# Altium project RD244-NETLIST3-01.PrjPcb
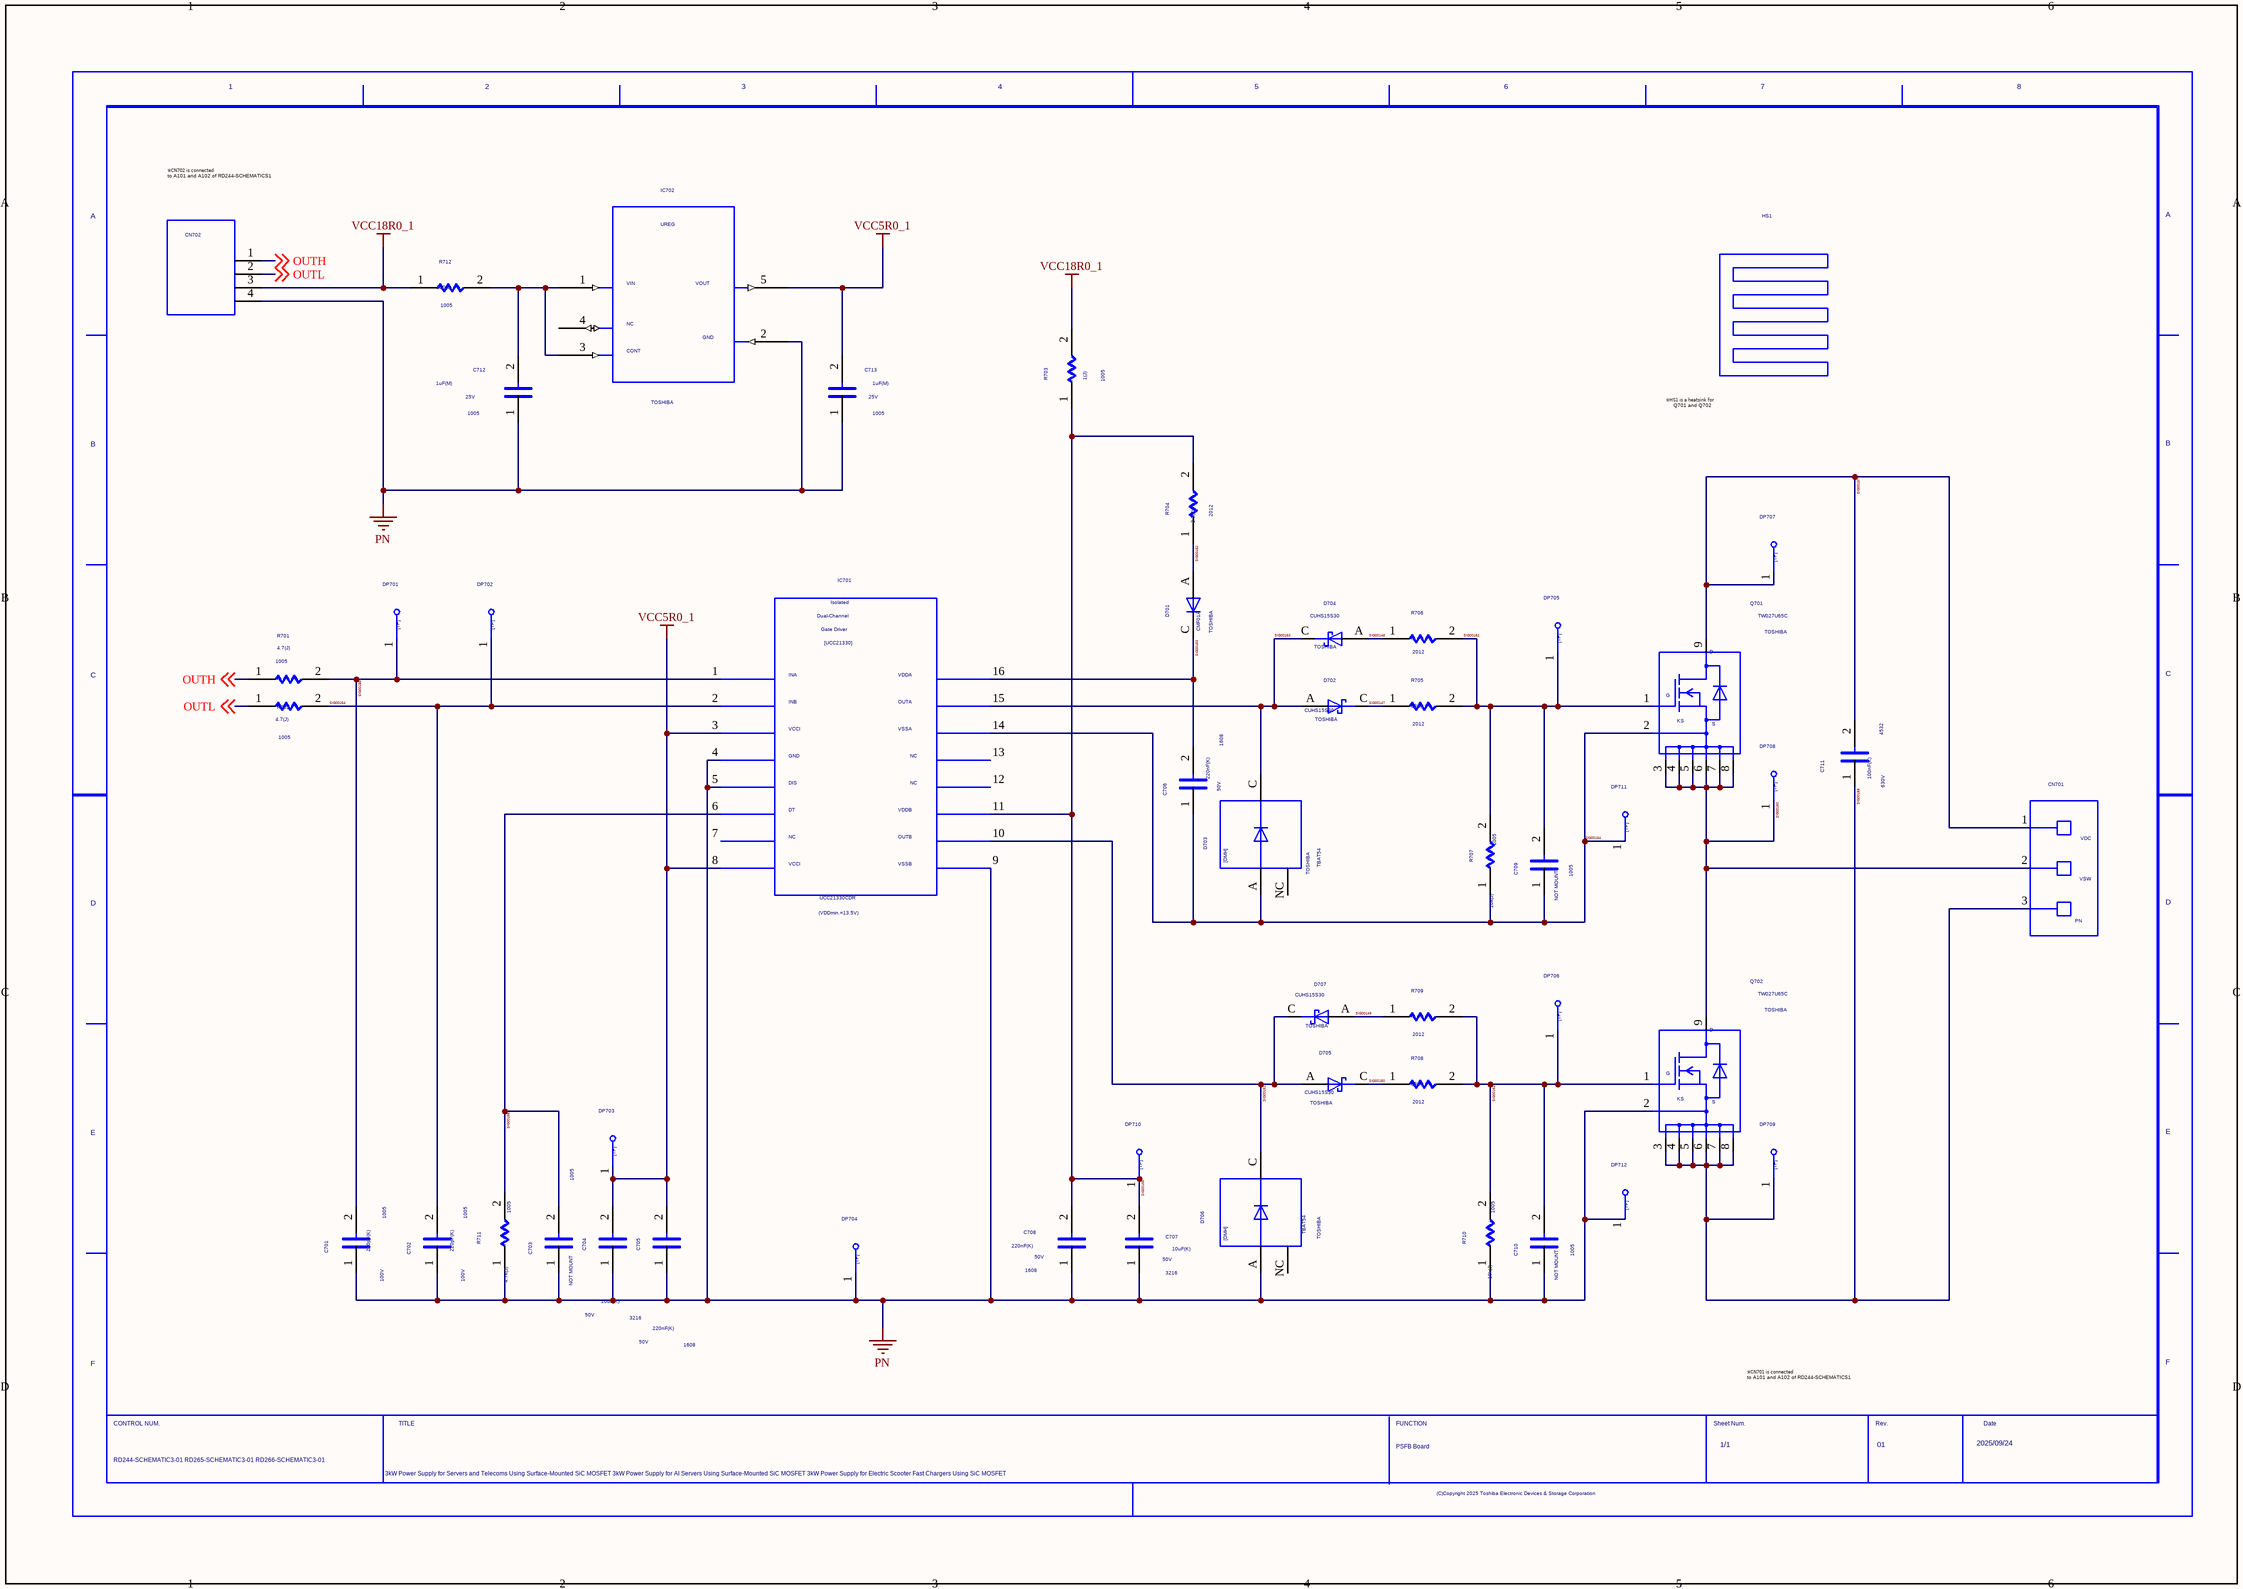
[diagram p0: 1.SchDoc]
1 sheet, 52 parts. Net scope: global (net labels, ports and power ports of the same name join across sheets).

## Sheet 1.SchDoc
size 420 x 297 mm

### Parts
C701  VAL1: 220pF(K)  VAL2: 100V  SIZECODESMD: 1005  (hidden comment: C)
C702  VAL1: 220pF(K)  VAL2: 100V  SIZECODESMD: 1005  (hidden comment: C)
C703  NOTMOUNT: NOT MOUNT  SIZECODESMD: 1005  (hidden comment: C)
C704  VAL1: 10uF(K)  VAL2: 50V  SIZECODESMD: 3216  (hidden comment: C)
C705  VAL1: 220nF(K)  VAL2: 50V  SIZECODESMD: 1608  (hidden comment: C1608)
C706  VAL1: 220nF(K)  VAL2: 50V  SIZECODESMD: 1608  (hidden comment: C1608)
C707  VAL1: 10uF(K)  VAL2: 50V  SIZECODESMD: 3216  (hidden comment: C)
C708  VAL1: 220nF(K)  VAL2: 50V  SIZECODESMD: 1608  (hidden comment: C1608)
C709  NOTMOUNT: NOT MOUNT  SIZECODESMD: 1005  (hidden comment: C)
C710  NOTMOUNT: NOT MOUNT  SIZECODESMD: 1005  (hidden comment: C)
C711  VAL1: 100nF(K)  VAL2: 630V  SIZECODESMD: 4532  (hidden comment: C)
C712  VAL1: 1uF(M)  VAL2: 25V  SIZECODESMD: 1005  (hidden comment: C)
C713  VAL1: 1uF(M)  VAL2: 25V  SIZECODESMD: 1005  (hidden comment: C)
CN701  RD-244_CN_from_FB  (value not drawn)
CN702  TSW-104-08-G-S-RA  (value not drawn)
D701  USERCOMPTEXT3: TOSHIBA  VAL3: CMF01A  (hidden comment: D)
D702  USERCOMPTEXT3: TOSHIBA  (hidden comment: CUHS15S30)
D703  USERCOMPTEXT3: TOSHIBA  VAL3: TBAT54  (hidden comment: DMH)
D704  USERCOMPTEXT3: TOSHIBA  (hidden comment: CUHS15S30)
D705  USERCOMPTEXT3: TOSHIBA  (hidden comment: CUHS15S30)
D706  USERCOMPTEXT3: TOSHIBA  VAL3: TBAT54  (hidden comment: DMH)
D707  USERCOMPTEXT3: TOSHIBA  (hidden comment: CUHS15S30)
DP701  TP  (value not drawn)
DP702  TP  (value not drawn)
DP703  TP  (value not drawn)
DP704  TP  (value not drawn)
DP705  TP  (value not drawn)
DP706  TP  (value not drawn)
DP707  TP  (value not drawn)
DP708  TP  (value not drawn)
DP709  TP  (value not drawn)
DP710  TP  (value not drawn)
DP711  TP  (value not drawn)
DP712  TP  (value not drawn)
HS1  UB3040-6B  (value not drawn)
IC701  VAL3: UCC21330CDR  USERCOMPTEXT1: (VDDmin.=13.5V)  (hidden comment: UCC21330)
IC702  USERCOMPTEXT3: TOSHIBA  (hidden comment: TCR1HF50B)
Q701  VAL3: TW027U65C  USERCOMPTEXT3: TOSHIBA  (hidden comment: NCHMOSFET_TOLL-02)
Q702  VAL3: TW027U65C  USERCOMPTEXT3: TOSHIBA  (hidden comment: NCHMOSFET_TOLL-02)
R701  VAL1: 4.7(J)  SIZECODESMD: 1005  (hidden comment: R)
R702  VAL1: 4.7(J)  SIZECODESMD: 1005  (hidden comment: R)
R703  VAL1: 1(J)  SIZECODESMD: 1005  (hidden comment: R)
R704  VAL1: 2.2(J)  SIZECODESMD: 2012  (hidden comment: R)
R705  VAL1: 33(J)  SIZECODESMD: 2012  (hidden comment: R)
R706  VAL1: 0  SIZECODESMD: 2012  (hidden comment: R)
R707  VAL1: 10k(J)  SIZECODESMD: 1005  (hidden comment: R)
R708  VAL1: 33(J)  SIZECODESMD: 2012  (hidden comment: R)
R709  VAL1: 0  SIZECODESMD: 2012  (hidden comment: R)
R710  VAL1: 10k(J)  SIZECODESMD: 1005  (hidden comment: R)
R711  VAL1: 4.7k(J)  SIZECODESMD: 1005  (hidden comment: R)
R712  VAL1: 100(J)  SIZECODESMD: 1005  (hidden comment: R)
U?  DATE: 2025/09/24  DRAWINGNUMBER: RD244-SCHEMATIC3-01 / RD265-SCHEMATIC3-01 / RD266-SCHEMATIC3-01  TITLE: 3kW Power Supply for Servers and Telecoms Using Surface-Mounted SiC MOSFET / 3kW Power Supply for AI Servers Using Surface-Mounted SiC MOSFET / 3kW Power Supply for Electric Scooter Fast Chargers Using SiC MOSFET  FUNCTION: PSFB Board  SHEETNUMBER: 1/1  REVISION: 01  (hidden comment: WAKU_DEF100)

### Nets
PN: C701.1 C702.1 C703.1 C704.1 C705.1 C707.1 C708.1 C710.1 C712.1 C713.1 CN702.4 D706.A DP704.1 DP712.1 IC701.4 IC701.5 IC701.9 IC702.2 Q702.2 R710.1 R711.1
VCC5R0_1: C704.2 C705.2 C713.2 DP703.1 IC701.3 IC701.8 IC702.5
VCC18R0_1: CN702.3 R703.2 R712.1
OUTH: CN702.1 R701.1 ; off-sheet OUTH
OUTL: CN702.2 R702.1 ; off-sheet OUTL
SIG00147: D702.C R705.1
SIG00148: D704.A R706.1
SIG00149: D707.A R709.1
SIG00150: D705.C R708.1
SIG00151: D705.A D706.C D707.C IC701.10
SIG00152: D701.A R704.1
SIG00153: C706.2 D701.C IC701.16
SIG00154: C702.2 DP702.1 IC701.2 R702.2
SIG00155: C701.2 DP701.1 IC701.1 R701.2
SIG00156: C703.2 IC701.6 R711.2
SIG00157: C711.2 CN701.1 DP707.1 Q701.9
SIG00158: C711.1 CN701.3 DP709.1 Q702.3 Q702.4 Q702.5 Q702.6 Q702.7 Q702.8
SIG00159: C712.2 IC702.1 IC702.3 R712.2
SIG00160: CN701.2 DP708.1 Q701.3 Q701.4 Q701.5 Q701.6 Q701.7 Q701.8 Q702.9
SIG00161: C710.2 DP706.1 Q702.1 R708.2 R709.2 R710.2
SIG00162: C709.2 DP705.1 Q701.1 R705.2 R706.2 R707.2
SIG00163: D702.A D703.C D704.C IC701.15
SIG00164: C706.1 C709.1 D703.A DP711.1 IC701.14 Q701.2 R707.1
SIG00165: C707.2 C708.2 DP710.1 IC701.11 R703.1 R704.2

Not connected (* = marked no-connect by the designer): D703 NC; D706 NC; IC701 7 12 13; IC702 4

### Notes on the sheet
- ※CN702 is connected
  to A101 and A102 of RD244-SCHEMATICS1
- ※HS1 is a heatsink for
  Q701 and Q702
- ※CN701 is connected
  to A101 and A102 of RD244-SCHEMATICS1

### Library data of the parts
C701 C702 = C_Dup1: OriginalSymbolOrigin: (2540,7620); COMP: PRT_52; VAL3: GRM155R72A221KA01; MAXGCOUNT: 1; SAVECOUNT: 0
C703 C709 C710 = C_Dup1: VAL1: 220pF(K); VAL2: 100V; OriginalSymbolOrigin: (2540,7620); COMP: PRT_52; VAL3: GRM155R72A221KA01; MAXGCOUNT: 1; SAVECOUNT: 0
C704 C707 = C_Dup1: OriginalSymbolOrigin: (2540,7620); COMP: PRT_46; VAL3: C3216X7R1H106K160AC; MAXGCOUNT: 1; SAVECOUNT: 0
C705 C706 C708 = C1608: SQ_PART_MODEL: CON_220N; TIME: 10:25:11; UPDATEUSER: t4887876; UPDATETIME: 06:19:09; SAVECOUNT: 10; VAL3: C1608X7R1H224K080AB; OriginalSymbolOrigin: (2540,7620); CHIPSIZE: 1005; MAXGCOUNT: 1; ADSCNVFLAG: ON; ADSCOMPONENTNAME: C_1005
C711 = C: SQ_PART_MODEL: CON_100N; OriginalSymbolOrigin: (2540,7620); MAXGCOUNT: 1; COMP: GRJ43DR72J104KWJ1K; ADSCNVFLAG: ON; ADSCOMPONENTNAME: C_4532; SAVECOUNT: 0
C712 C713 = C_Dup1: SQ_PART_MODEL: CON_1U; OriginalSymbolOrigin: (2540,7620); COMP: PRT_52; VAL3: GRM155C81E105ME11; MAXGCOUNT: 1; ADSCNVFLAG: ON; ADSCOMPONENTNAME: C_1608; SAVECOUNT: 0
CN701 = RD-244_CN_FROM_FB: TIME: 11:34:46; UPDATEUSER: t5459927; UPDATETIME: 14:01:19; SAVECOUNT: 38; SAVEAREA0: -20981,-344,43891,33349; VAL3: PCB_Pad; OriginalSymbolOrigin: (0,25400)
CN702 = TSW-104-08-G-S-RA: SAVEAREA0: -8845,-265,28754,23475; SAVECOUNT: 24; TIME: 13:28:28; UPDATEUSER: t4887876; UPDATETIME: 10:06:27; OriginalSymbolOrigin: (2540,20320)
D701 = D: SAVEAREA0: -225,-91,12804,7836; SAVECOUNT: 3; TIME: 14:49:55; UPDATEUSER: 19870035; UPDATETIME: 14:20:16; OriginalSymbolOrigin: (5080,5080); USERCOMPTEXT2: 600V,2A; COMP: PRT_14; MAXGCOUNT: 1
D702 D704 D705 D707 = CUHS15S30: SAVEAREA0: -4630,-153,17114,13055; TIME: 14:49:55; UPDATEUSER: t4887876; UPDATETIME: 17:19:09; SAVECOUNT: 10; OriginalSymbolOrigin: (5080,5080); USERCOMPTEXT2: 30V,1.5A
D703 D706 = DMH: SAVEAREA0: -4931,-287,27399,20979; TIME: 08:58:08; UPDATEUSER: kishi-s; UPDATETIME: 09:01:52; SAVECOUNT: 2; OriginalSymbolOrigin: (5080,17780); USERCOMPTEXT2: 30V,0.2A; COMP: PRT_25
DP701-DP712 = TP: TIME: 16:12:21; UPDATEUSER: fukuda-y; UPDATETIME: 16:18:11; SAVECOUNT: 2; SAVEAREA0: -242,-92,12810,7836; OriginalSymbolOrigin: (0,7620); USERCOMPTEXT1: Φ1.5mm; COMP: DTP815
HS1 = UB3040-6B: TIME: 14:03:26; UPDATEUSER: t4887876; UPDATETIME: 11:08:23; SAVECOUNT: 67; SAVEAREA0: -22316,-9081,43667,39223; VAL2: W30mm*L40mm*H6mm; OriginalSymbolOrigin: (5080,21590)
IC701 = UCC21330: SAVEAREA0: -23586,-777,74646,64019; SAVECOUNT: 95; TIME: 14:04:55; UPDATEUSER: t4887876; UPDATETIME: 15:12:35; OriginalSymbolOrigin: (-2540,55880)
IC702 = TCR1HF50B: SAVEAREA0: -444,-3509,43701,41525; TIME: 18:31:00; UPDATEUSER: t6860224; UPDATETIME: 18:26:20; SAVECOUNT: 17; VAL1: Linear Regulator; OriginalSymbolOrigin: (7620,35560)
Q701 Q702 = NCHMOSFET_TOLL-02: PARTS: 1; CLASS: DISCRETE; PKG_TYPE: DISC; LEVEL: STD; DEVICENAME: 2SJ132; SAVECOUNT: 33; SAVEAREA0: -7753,-3954,18724,15429; TIME: 17:22:02; UPDATEUSER: t5459927; UPDATETIME: 20:09:04; COMP: NchMOSFET_TOLL-01; CHIPSET: TOLL; VAL1: ※定格電圧を記入する; OriginalSymbolOrigin: (0,22860)
R701 R702 = R: VAL2: 63mW; OriginalSymbolOrigin: (5080,5080); COMP: GDM010004481; VAL3: RK73B1ETTP4R7J; CHIPSIZE: 1608; MAXGCOUNT: 1; SAVECOUNT: 0
R703 = R: VAL2: 63mW; OriginalSymbolOrigin: (5080,5080); COMP: GDM010004481; VAL3: RK73B1ETTP1R0J; CHIPSIZE: 1608; MAXGCOUNT: 1; SAVECOUNT: 0
R704 = R: VAL2: 125mW; OriginalSymbolOrigin: (5080,5080); COMP: R2012; VAL3: SG732ATTD2R2K; CHIPSIZE: 3216; MAXGCOUNT: 1; SAVECOUNT: 0
R705 R708 = R: VAL2: 500mW; OriginalSymbolOrigin: (5080,5080); COMP: R2012; VAL3: RK73B2ATTD330J; CHIPSIZE: 3216; MAXGCOUNT: 1; SAVECOUNT: 0
R706 R709 = R: VAL2: 500mW; OriginalSymbolOrigin: (5080,5080); COMP: R2012; VAL3: RK73Z2ATTD; CHIPSIZE: 3216; MAXGCOUNT: 1
R707 R710 = R: VAL2: 63mW; OriginalSymbolOrigin: (5080,5080); COMP: GDM010004481; VAL3: RK73B1ETTP103J; CHIPSIZE: 1608; MAXGCOUNT: 1; SAVECOUNT: 0
R711 = R: VAL2: 63mW; OriginalSymbolOrigin: (5080,5080); COMP: GDM010004481; VAL3: RK73B1ETTP472J; CHIPSIZE: 1608; MAXGCOUNT: 1; SAVECOUNT: 0
R712 = R: VAL2: 63mW; OriginalSymbolOrigin: (5080,5080); COMP: GDM010004481; VAL3: RK73B1ETTP101J; CHIPSIZE: 1608; MAXGCOUNT: 1; SAVECOUNT: 0
U? = WAKU_DEF100: PLOTTIME: HH:MM; SAVEAREA0: -63393,-16950,474261,314592; TIME: 14:30:25; UPDATEUSER: t5459927; UPDATETIME: 14:02:38; SAVECOUNT: 5; OriginalSymbolOrigin: (10160,284480); SHTSAVECOUNT: 149; PAGENUMBER: 1; DESIGNED: TOSHIBA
